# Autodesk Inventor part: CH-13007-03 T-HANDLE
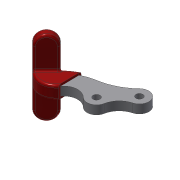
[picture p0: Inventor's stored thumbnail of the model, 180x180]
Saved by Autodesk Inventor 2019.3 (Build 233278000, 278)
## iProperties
Created: 2012-09
Part Number: CH-13007-03 T-HANDLE
Material: Ogólny
Document SubType Name: Modeling
Designer: CADENGINEERING4
Density: 1 g/cm^3
Appearance: Domyślna
Author: CADENGINEERING4
Revision Number: ÈÎºÎ
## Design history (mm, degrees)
feature "Ô²½Ç7"
node "Bryła1"
